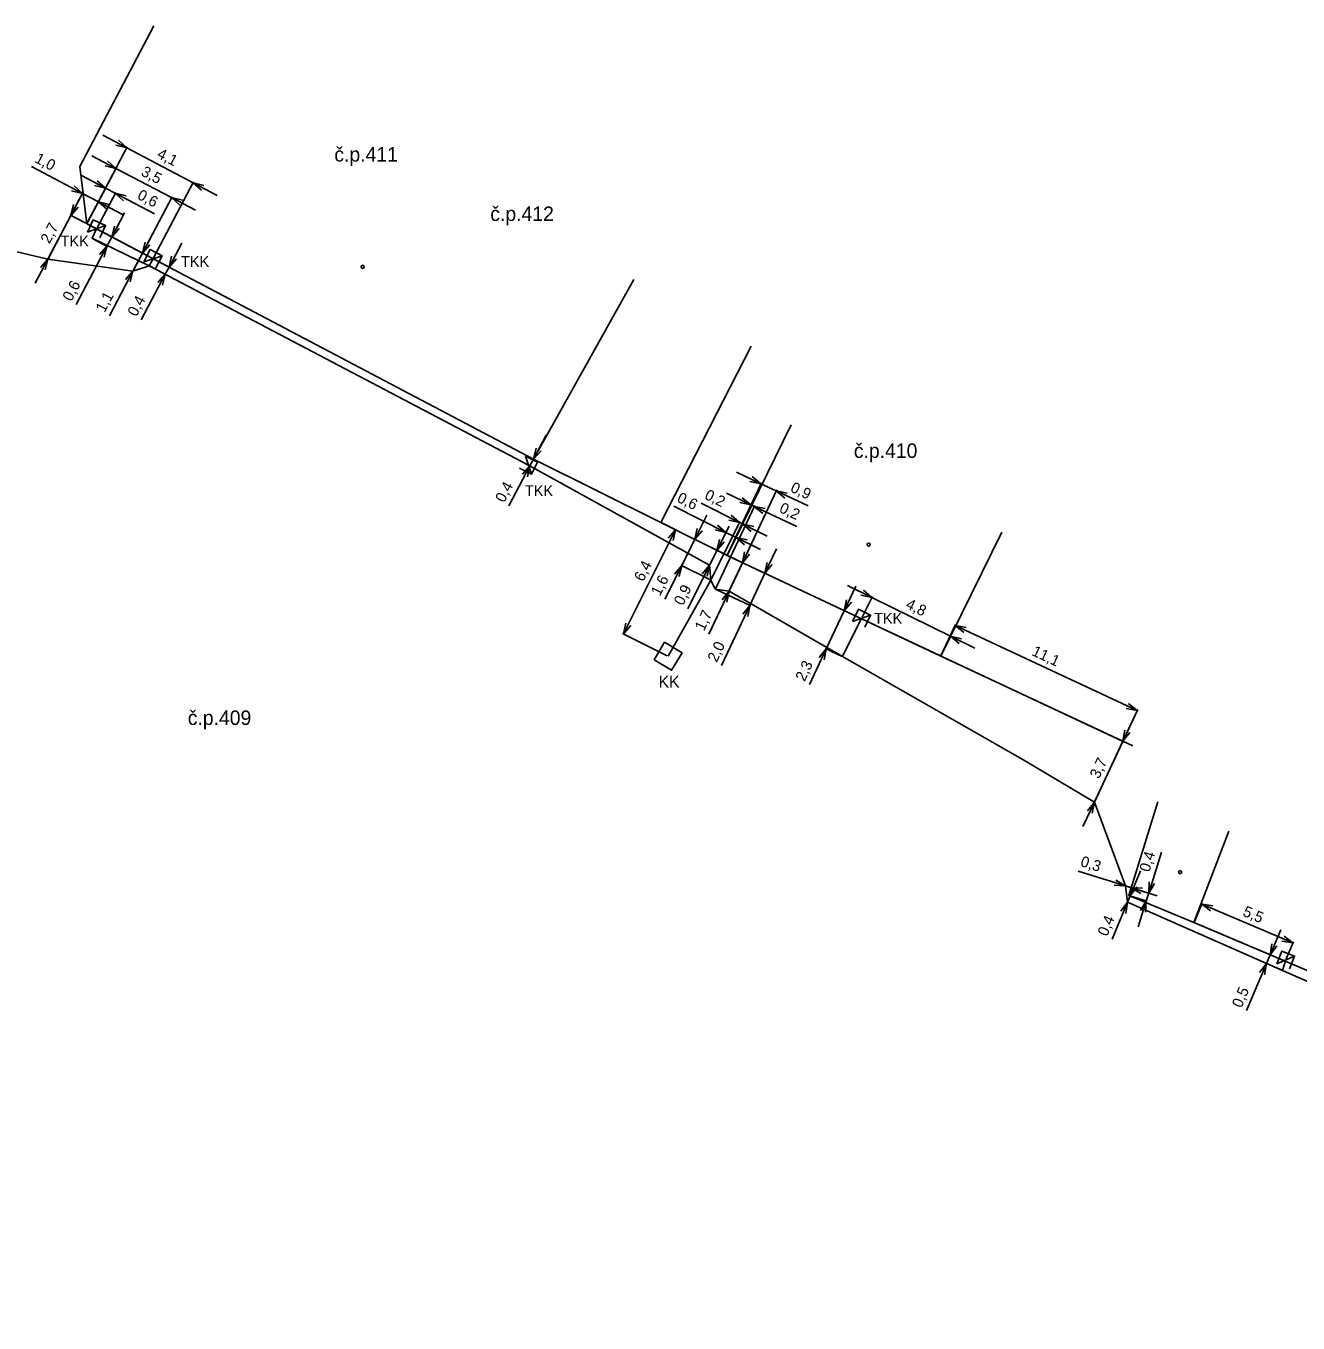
# Model space of a CAD drawing. Extents: x -770877 to -770229, y -1050342 to -1050226.
# Drawn here: x -770785.2 to -770714.9, y -1050335.5 to -1050263.9 of the extents above; entities that cross this region are included whole.
import ezdxf

# ---------------------------------------------------------------- set-up
doc = ezdxf.new("R2010")
doc.units = 0
for name, color, linetype in [('f001_pol_linie', 7, 'Continuous'), ('f001_pol_znacky', 7, 'Continuous'), ('f003_opt_sit_texty', 7, 'Continuous'), ('f003_opt_sit_znacky', 7, 'Continuous'), ('f006_kbv_texty', 7, 'Continuous'), ('f006_kbv_znacky', 7, 'Continuous'), ('f006_osa_trasy', 7, 'Continuous'), ('f006_stp_koty', 7, 'Continuous'), ('Inspire adresy', 7, 'Continuous')]:
    doc.layers.add(name, color=color, linetype=linetype)

msp = doc.modelspace()

# ---------------------------------------------------------------- linework, layer by layer
at = {"layer": 'f001_pol_linie'}
for points in [[(-770778.14, -1050263.87), (-770782.23, -1050271.64), (-770781.85, -1050274.8), (-770757.17, -1050287.8), (-770751.63, -1050277.88)], [(-770750.135, -1050291.291), (-770745.15, -1050281.56)], [(-770742.95, -1050285.91), (-770746.48, -1050293.12), (-770734.68, -1050298.68), (-770731.3, -1050291.84)], [(-770757.17, -1050287.8), (-770750.135, -1050291.291), (-770746.48, -1050293.12)], [(-770734.68, -1050298.68), (-770724.064, -1050303.641)], [(-770722.68, -1050306.73), (-770724.29, -1050311.9), (-770720.69, -1050313.39), (-770718.76, -1050308.35)], [(-770720.69, -1050313.39), (-770700.91, -1050321.78), (-770684.19, -1050327.86), (-770669.22, -1050331.86), (-770647.86, -1050335.52)]]:
    msp.add_lwpolyline(points, dxfattribs=at)
at = {"layer": 'f001_pol_znacky'}
for centre in [(-770766.61, -1050277.175), (-770738.659, -1050292.519), (-770721.455, -1050310.616)]:
    msp.add_circle(centre, 0.0875, dxfattribs=at)
at = {"layer": 'f003_opt_sit_znacky'}
for p, q in [((-770781.806, -1050275.267), (-770780.814, -1050274.893)), ((-770778.695, -1050276.892), (-770777.685, -1050276.568)), ((-770757.62, -1050287.628), (-770757.28, -1050288.632)), ((-770739.549, -1050296.769), (-770738.551, -1050296.411)), ((-770716.106, -1050315.673), (-770715.134, -1050315.247))]:
    msp.add_line(p, q, dxfattribs=at)
for points in [[(-770781.123, -1050275.576), (-770780.814, -1050274.893), (-770781.497, -1050274.584), (-770781.806, -1050275.267)], [(-770778.028, -1050277.235), (-770777.685, -1050276.568), (-770778.352, -1050276.225), (-770778.695, -1050276.892)], [(-770757.952, -1050288.3), (-770757.28, -1050288.632), (-770756.948, -1050287.96), (-770757.62, -1050287.628)], [(-770738.871, -1050297.089), (-770738.551, -1050296.411), (-770739.229, -1050296.091), (-770739.549, -1050296.769)], [(-770715.407, -1050315.946), (-770715.134, -1050315.247), (-770715.833, -1050314.974), (-770716.106, -1050315.673)]]:
    msp.add_lwpolyline(points, dxfattribs=at)
at = {"layer": 'f006_kbv_znacky'}
msp.add_lwpolyline([(-770749.93, -1050297.917), (-770750.513, -1050298.88), (-770749.55, -1050299.463), (-770748.967, -1050298.5)], close=True, dxfattribs=at)
at = {"layer": 'f006_osa_trasy'}
for points in [[(-770792.25, -1050274.81), (-770784, -1050276.75), (-770779.3, -1050277.41), (-770778.4, -1050277.12), (-770757.45, -1050288.13)], [(-770778.4, -1050277.12), (-770781.56, -1050275.6), (-770781.31, -1050275.08)], [(-770778.4, -1050277.12), (-770778.19, -1050276.73)], [(-770757.45, -1050288.13), (-770747.45, -1050293.66), (-770747.38, -1050294.48), (-770749.74, -1050298.69)], [(-770747.38, -1050294.48), (-770747.13, -1050294.98), (-770746.37, -1050295.09), (-770740.11, -1050298.7), (-770739.05, -1050296.59)], [(-770740.11, -1050298.7), (-770730.19, -1050304.38), (-770726.19, -1050306.74), (-770724.48, -1050311.37), (-770724.37, -1050312.28), (-770715.81, -1050316.04)], [(-770715.81, -1050316.04), (-770715.62, -1050315.46)], [(-770715.81, -1050316.04), (-770701.13, -1050322.48), (-770693.16, -1050325.44), (-770689.11, -1050326.94), (-770684.37, -1050328.47), (-770676.79, -1050330.47), (-770669.21, -1050332.47), (-770659.8, -1050334.11), (-770659.66, -1050333.31)]]:
    msp.add_lwpolyline(points, dxfattribs=at)
at = {"layer": 'f006_stp_koty'}
for p, q in [((-770780.965, -1050269.901), (-770779.638, -1050270.6)), ((-770781.794, -1050274.694), (-770779.61, -1050270.547)), ((-770775.977, -1050272.528), (-770779.638, -1050270.6)), ((-770781.563, -1050271.037), (-770780.236, -1050271.736)), ((-770784.908, -1050271.636), (-770782.089, -1050273.121)), ((-770782.14, -1050272.133), (-770780.813, -1050272.832)), ((-770781.822, -1050274.747), (-770780.208, -1050271.683)), ((-770780.236, -1050271.736), (-770777.164, -1050273.355)), ((-770781.794, -1050274.694), (-770780.785, -1050272.779)), ((-770780.275, -1050273.115), (-770780.813, -1050272.832)), ((-770778.162, -1050276.677), (-770775.949, -1050272.475)), ((-770774.65, -1050273.227), (-770775.977, -1050272.528)), ((-770783.972, -1050276.697), (-770782.061, -1050273.068)), ((-770782.03, -1050273.01), (-770782.729, -1050274.337)), ((-770781.21, -1050273.584), (-770782.089, -1050273.121)), ((-770781.822, -1050274.747), (-770781.182, -1050273.531)), ((-770781.282, -1050275.027), (-770780.247, -1050273.062)), ((-770779.883, -1050274.283), (-770781.21, -1050273.584)), ((-770778.116, -1050274.253), (-770780.275, -1050273.115)), ((-770779.272, -1050277.357), (-770777.136, -1050273.302)), ((-770775.837, -1050274.054), (-770777.164, -1050273.355)), ((-770784, -1050276.75), (-770782.729, -1050274.337)), ((-770781.903, -1050274.772), (-770782.782, -1050274.309)), ((-770779.767, -1050274.202), (-770780.466, -1050275.529)), ((-770781.797, -1050274.828), (-770780.413, -1050275.557)), ((-770781.797, -1050274.828), (-770778.725, -1050276.446)), ((-770781.797, -1050274.828), (-770777.253, -1050277.221)), ((-770781.507, -1050275.628), (-770780.68, -1050276.064)), ((-770780.733, -1050276.036), (-770780.466, -1050275.529)), ((-770778.079, -1050275.091), (-770778.778, -1050276.418)), ((-770782.433, -1050279.264), (-770780.733, -1050276.036)), ((-770779.3, -1050277.41), (-770778.778, -1050276.418)), ((-770776.607, -1050275.866), (-770777.306, -1050277.193)), ((-770784.699, -1050278.077), (-770784, -1050276.75)), ((-770778.347, -1050277.148), (-770777.461, -1050277.615)), ((-770777.514, -1050277.587), (-770777.306, -1050277.193)), ((-770780.6, -1050279.877), (-770779.3, -1050277.41)), ((-770778.839, -1050280.104), (-770777.514, -1050277.587)), ((-770756.471, -1050286.473), (-770757.17, -1050287.8)), ((-770757.367, -1050288.174), (-770757.17, -1050287.8)), ((-770758.529, -1050290.381), (-770757.367, -1050288.174)), ((-770757.397, -1050288.158), (-770757.314, -1050288.202)), ((-770745.969, -1050288.517), (-770744.612, -1050289.157)), ((-770746.454, -1050293.066), (-770744.587, -1050289.102)), ((-770744.612, -1050289.157), (-770743.763, -1050289.557)), ((-770746.518, -1050289.681), (-770745.161, -1050290.321)), ((-770746.344, -1050295.036), (-770743.737, -1050289.503)), ((-770742.004, -1050290.386), (-770743.763, -1050289.557)), ((-770749.429, -1050290.398), (-770746.541, -1050291.843)), ((-770747.904, -1050290.238), (-770745.787, -1050291.297)), ((-770747.104, -1050294.926), (-770744.95, -1050290.354)), ((-770746.454, -1050293.066), (-770745.135, -1050290.266)), ((-770745.161, -1050290.321), (-770744.976, -1050290.408)), ((-770742.622, -1050291.517), (-770744.976, -1050290.408)), ((-770750.081, -1050291.318), (-770749.271, -1050291.723)), ((-770747.593, -1050290.886), (-770748.264, -1050292.227)), ((-770747.353, -1050294.426), (-770745.761, -1050291.244)), ((-770746.368, -1050291.499), (-770747.04, -1050292.84)), ((-770746.453, -1050293.066), (-770745.585, -1050291.331)), ((-770745.612, -1050291.385), (-770745.787, -1050291.297)), ((-770744.27, -1050292.056), (-770745.612, -1050291.385)), ((-770752.207, -1050297.456), (-770749.325, -1050291.696)), ((-770748.988, -1050293.675), (-770748.264, -1050292.227)), ((-770746.534, -1050293.093), (-770748.318, -1050292.2)), ((-770747.423, -1050293.606), (-770746.514, -1050291.79)), ((-770745.981, -1050292.123), (-770746.541, -1050291.843)), ((-770746.453, -1050293.066), (-770745.954, -1050292.07)), ((-770744.64, -1050292.795), (-770745.981, -1050292.123)), ((-770744.991, -1050292.163), (-770745.63, -1050293.52)), ((-770747.45, -1050293.66), (-770747.04, -1050292.84)), ((-770746.534, -1050293.093), (-770747.093, -1050292.813)), ((-770743.747, -1050292.749), (-770744.387, -1050294.106)), ((-770749.918, -1050295.534), (-770748.988, -1050293.675)), ((-770747.434, -1050294.453), (-770749.042, -1050293.648)), ((-770748.652, -1050296.062), (-770747.45, -1050293.66)), ((-770746.426, -1050293.146), (-770744.332, -1050294.132)), ((-770746.426, -1050293.146), (-770745.576, -1050293.546)), ((-770746.37, -1050295.09), (-770745.63, -1050293.52)), ((-770745.222, -1050295.879), (-770744.387, -1050294.106)), ((-770747.487, -1050297.461), (-770746.37, -1050295.09)), ((-770747.076, -1050295.006), (-770745.168, -1050295.905)), ((-770739.368, -1050294.813), (-770740.007, -1050296.17)), ((-770739.826, -1050294.774), (-770738.481, -1050295.439)), ((-770739.023, -1050296.536), (-770738.455, -1050295.385)), ((-770738.481, -1050295.439), (-770734.139, -1050297.585)), ((-770746.782, -1050299.19), (-770745.222, -1050295.879)), ((-770741.001, -1050298.28), (-770740.007, -1050296.17)), ((-770734.734, -1050298.654), (-770740.062, -1050296.144)), ((-770734.655, -1050298.626), (-770733.861, -1050296.927)), ((-770733.886, -1050296.981), (-770723.827, -1050301.682)), ((-770749.794, -1050298.663), (-770752.261, -1050297.429)), ((-770734.653, -1050298.626), (-770734.112, -1050297.531)), ((-770732.794, -1050298.249), (-770734.139, -1050297.585)), ((-770741.928, -1050300.246), (-770741.001, -1050298.28)), ((-770740.164, -1050298.674), (-770741.056, -1050298.254)), ((-770734.626, -1050298.705), (-770724.566, -1050303.406)), ((-770726.165, -1050306.686), (-770723.801, -1050301.628)), ((-770723.985, -1050302.022), (-770724.62, -1050303.381)), ((-770726.19, -1050306.74), (-770724.62, -1050303.381)), ((-770726.825, -1050308.099), (-770726.19, -1050306.74)), ((-770722.491, -1050309.516), (-770723.193, -1050311.771)), ((-770727.094, -1050310.556), (-770724.48, -1050311.37)), ((-770723.65, -1050310.541), (-770724.224, -1050311.927)), ((-770724.48, -1050311.37), (-770724.156, -1050311.471)), ((-770724.423, -1050311.388), (-770723.136, -1050311.789)), ((-770724.272, -1050311.843), (-770724.138, -1050311.414)), ((-770722.724, -1050311.917), (-770724.156, -1050311.471)), ((-770725.211, -1050314.311), (-770724.37, -1050312.28)), ((-770724.37, -1050312.28), (-770724.224, -1050311.927)), ((-770724.235, -1050311.923), (-770724.169, -1050311.95)), ((-770724.233, -1050311.918), (-770723.27, -1050312.218)), ((-770723.773, -1050313.632), (-770723.327, -1050312.2)), ((-770723.327, -1050312.2), (-770723.193, -1050311.771)), ((-770720.667, -1050313.335), (-770720.241, -1050312.331)), ((-770720.264, -1050312.386), (-770715.223, -1050314.524)), ((-770720.635, -1050313.413), (-770716.427, -1050315.198)), ((-770715.897, -1050313.794), (-770716.483, -1050315.175)), ((-770715.597, -1050315.405), (-770715.2, -1050314.469)), ((-770716.691, -1050315.666), (-770716.483, -1050315.175)), ((-770717.793, -1050318.264), (-770716.691, -1050315.666)), ((-770715.865, -1050316.017), (-770716.746, -1050315.643))]:
    msp.add_line(p, q, dxfattribs=at)
for points in [[(-770780.099, -1050270.187), (-770779.638, -1050270.6), (-770780.238, -1050270.453)], [(-770780.697, -1050271.324), (-770780.236, -1050271.736), (-770780.837, -1050271.589)], [(-770782.55, -1050272.709), (-770782.089, -1050273.121), (-770782.689, -1050272.974)], [(-770781.274, -1050272.42), (-770780.813, -1050272.832), (-770781.414, -1050272.685)], [(-770775.516, -1050272.94), (-770775.977, -1050272.528), (-770775.376, -1050272.675)], [(-770780.749, -1050273.997), (-770781.21, -1050273.584), (-770780.609, -1050273.731)], [(-770779.814, -1050273.528), (-770780.275, -1050273.115), (-770779.674, -1050273.262)], [(-770776.703, -1050273.767), (-770777.164, -1050273.355), (-770776.563, -1050273.502)], [(-770782.317, -1050273.876), (-770782.729, -1050274.337), (-770782.582, -1050273.736)], [(-770780.053, -1050275.068), (-770780.466, -1050275.529), (-770780.319, -1050274.928)], [(-770781.145, -1050276.497), (-770780.733, -1050276.036), (-770780.88, -1050276.637)], [(-770778.365, -1050275.957), (-770778.778, -1050276.418), (-770778.631, -1050275.818)], [(-770784.412, -1050277.211), (-770784, -1050276.75), (-770784.147, -1050277.351)], [(-770776.894, -1050276.732), (-770777.306, -1050277.193), (-770777.16, -1050276.593)], [(-770779.712, -1050277.871), (-770779.3, -1050277.41), (-770779.447, -1050278.011)], [(-770777.926, -1050278.048), (-770777.514, -1050277.587), (-770777.661, -1050278.188)], [(-770756.758, -1050287.339), (-770757.17, -1050287.8), (-770757.023, -1050287.199)], [(-770757.779, -1050288.635), (-770757.367, -1050288.174), (-770757.514, -1050288.775)], [(-770745.091, -1050288.765), (-770744.612, -1050289.157), (-770745.219, -1050289.036)], [(-770745.64, -1050289.929), (-770745.161, -1050290.321), (-770745.768, -1050290.201)], [(-770743.284, -1050289.948), (-770743.763, -1050289.557), (-770743.156, -1050289.677)], [(-770744.497, -1050290.799), (-770744.976, -1050290.408), (-770744.369, -1050290.528)], [(-770747.01, -1050291.441), (-770746.541, -1050291.843), (-770747.145, -1050291.709)], [(-770746.257, -1050290.895), (-770745.787, -1050291.297), (-770746.391, -1050291.163)], [(-770745.142, -1050291.788), (-770745.612, -1050291.385), (-770745.008, -1050291.52)], [(-770749.728, -1050292.166), (-770749.325, -1050291.696), (-770749.459, -1050292.3)], [(-770747.861, -1050291.758), (-770748.264, -1050292.227), (-770748.129, -1050291.624)], [(-770746.637, -1050292.371), (-770747.04, -1050292.84), (-770746.905, -1050292.236)], [(-770745.512, -1050292.526), (-770745.981, -1050292.123), (-770745.378, -1050292.258)], [(-770745.239, -1050293.041), (-770745.63, -1050293.52), (-770745.51, -1050292.914)], [(-770749.391, -1050294.145), (-770748.988, -1050293.675), (-770749.123, -1050294.279)], [(-770747.853, -1050294.129), (-770747.45, -1050293.66), (-770747.584, -1050294.264)], [(-770743.995, -1050293.628), (-770744.387, -1050294.106), (-770744.267, -1050293.5)], [(-770746.761, -1050295.569), (-770746.37, -1050295.09), (-770746.49, -1050295.697)], [(-770738.953, -1050295.039), (-770738.481, -1050295.439), (-770739.086, -1050295.308)], [(-770739.616, -1050295.691), (-770740.007, -1050296.17), (-770739.887, -1050295.563)], [(-770745.613, -1050296.358), (-770745.222, -1050295.879), (-770745.342, -1050296.486)], [(-770751.804, -1050296.986), (-770752.207, -1050297.456), (-770752.073, -1050296.852)], [(-770733.406, -1050297.371), (-770733.886, -1050296.981), (-770733.279, -1050297.099)], [(-770733.667, -1050297.985), (-770734.139, -1050297.585), (-770733.534, -1050297.716)], [(-770741.393, -1050298.759), (-770741.001, -1050298.28), (-770741.122, -1050298.887)], [(-770724.307, -1050301.292), (-770723.827, -1050301.682), (-770724.434, -1050301.564)], [(-770724.23, -1050302.901), (-770724.62, -1050303.381), (-770724.502, -1050302.774)], [(-770726.58, -1050307.22), (-770726.19, -1050306.74), (-770726.308, -1050307.347)], [(-770725.008, -1050311.048), (-770724.48, -1050311.37), (-770725.097, -1050311.335)], [(-770723.856, -1050311.43), (-770724.224, -1050311.927), (-770724.133, -1050311.316)], [(-770723.628, -1050311.792), (-770724.156, -1050311.471), (-770723.539, -1050311.506)], [(-770722.872, -1050311.242), (-770723.193, -1050311.771), (-770723.158, -1050311.153)], [(-770724.738, -1050312.777), (-770724.37, -1050312.28), (-770724.461, -1050312.892)], [(-770723.649, -1050312.728), (-770723.327, -1050312.2), (-770723.362, -1050312.817)], [(-770719.77, -1050312.758), (-770720.264, -1050312.386), (-770719.653, -1050312.482)], [(-770715.717, -1050314.152), (-770715.223, -1050314.524), (-770715.834, -1050314.428)], [(-770716.11, -1050314.681), (-770716.483, -1050315.175), (-770716.386, -1050314.564)], [(-770717.064, -1050316.16), (-770716.691, -1050315.666), (-770716.787, -1050316.277)]]:
    msp.add_lwpolyline(points, dxfattribs=at)

# ---------------------------------------------------------------- texts
at = {"layer": 'f003_opt_sit_texty'}
for p in [(-770783.294, -1050276.051), (-770776.643, -1050277.181), (-770757.649, -1050289.842), (-770738.362, -1050296.889)]:
    msp.add_text('TKK', height=0.6, dxfattribs=at).set_placement(p)
at = {"layer": 'f006_kbv_texty'}
msp.add_text('KK', height=0.65, dxfattribs=at).set_placement((-770750.265, -1050300.417))
at = {"layer": 'f006_stp_koty'}
for s, rotation, p in [('4,1', 332.22233, (-770778.017, -1050271.114)), ('1,0', 332.22233, (-770784.768, -1050271.371)), ('3,5', 332.22233, (-770778.897, -1050272.103)), ('0,6', 332.22233, (-770779.105, -1050273.393)), ('2,7', 62.22233, (-770783.911, -1050275.938)), ('0,6', 62.22233, (-770782.698, -1050279.124)), ('1,1', 62.22233, (-770780.865, -1050279.738)), ('0,4', 62.22233, (-770779.105, -1050279.964)), ('0,4', 62.22233, (-770758.795, -1050290.241)), ('0,9', 334.77082, (-770743.03, -1050289.571)), ('0,6', 333.41614, (-770749.294, -1050290.13)), ('0,2', 333.41614, (-770747.77, -1050289.97)), ('0,2', 334.77082, (-770743.647, -1050290.702)), ('6,4', 63.41614, (-770751.115, -1050294.603)), ('1,6', 63.41614, (-770750.187, -1050295.399)), ('0,9', 63.41614, (-770748.92, -1050295.927)), ('4,8', 333.70363, (-770736.661, -1050296.004)), ('1,7', 64.77082, (-770747.758, -1050297.333)), ('2,0', 64.77082, (-770747.053, -1050299.062)), ('11,1', 334.95268, (-770729.693, -1050298.61)), ('2,3', 64.77082, (-770742.199, -1050300.118)), ('3,7', 64.95268, (-770725.938, -1050305.492)), ('0,3', 342.70279, (-770727.005, -1050310.27)), ('0,4', 72.70279, (-770723.157, -1050310.644)), ('0,4', 67.51588, (-770725.488, -1050314.196)), ('5,5', 337.015, (-770718.04, -1050313.004)), ('0,5', 67.015, (-770718.069, -1050318.147))]:
    msp.add_text(s, height=0.6, rotation=rotation, dxfattribs=at).set_placement(p)
at = {"layer": 'Inspire adresy'}
for s, p in [('č.p.411', (-770768.174, -1050271.363)), ('č.p.412', (-770759.559, -1050274.643)), ('č.p.410', (-770739.479, -1050287.733)), ('č.p.409', (-770776.27, -1050302.483))]:
    msp.add_text(s, height=0.8, dxfattribs=at).set_placement(p)

doc.saveas('drawing.dxf')
